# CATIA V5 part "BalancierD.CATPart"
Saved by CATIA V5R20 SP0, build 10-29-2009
Part number: BalancierD
Bounding box of the stored display mesh (mm): x 0 to 1, y 23.251 to 27.405, z -0.749 to 6.528
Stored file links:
  C:\Users\MATT\Desktop\CATIA_Projet_IAO\CATIA FINAL\BalancierD.CATPart
  C:\Users\MATT\Desktop\CATIA_Projet_IAO\CATIA FINAL\mderemetz.CATProduct
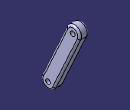
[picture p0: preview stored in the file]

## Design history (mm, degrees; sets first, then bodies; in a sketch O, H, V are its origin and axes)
External parameters (linked from other documents)
  External.AC = 3 mm
Set1
  Plane1 "Plan_Ref": linked copy from another document
  Point1 "B": linked copy from another document
  Point2 "F": linked copy from another document
  Plane2 "Plan_Sec": linked copy from another document
Body1 (main body)
  Sketch1 on Plane1, origin (0, 0, 0), H (0, 1, 0), V (0, 0, 1)
    construction line L1 (24.0001, 0) -> (26.6557, 5.779)
    point P1 (24.0001, 0)
    point P2 (26.6557, 5.779)
    line L2 (23.3186, 0.3132) -> (25.9743, 6.0921)
    line L3 (27.3372, 5.4658) -> (24.6816, -0.3132)
    arc A1 centre (26.6557, 5.779) radius 0.75 from (25.9743, 6.0921) to (27.3372, 5.4658) cw
    arc A2 centre (24.0001, 0) radius 0.75 from (24.6816, -0.3132) to (23.3186, 0.3132) cw
    reference projected point E1 (26.6557, 5.779) from Point1
    reference projected point E2 (24.0001, 0) from Point2
    distance L3 L2 = 1.5 {= 1.5*External.AC /3}
    tangency: A1 L2, A2 L2, A1 L3, A2 L3
    parallelism: L1 L2
    coincidence: P2 E1, P1 E2
  Pad1: profile Sketch1, direction (1, 0, 0), up to Plane2
  Sketch2 on end face of Pad1, origin (1, 25.1072, 2.6065), H (0, 1, 0), V (0, 0, 1)
    point P1 (1.5486, 3.1724)
    reference projected point E1 (1.5486, 3.1724) from Point1
    coincidence: P1 E1
  Hole1: placed by Sketch2, at (1, 26.6557, 5.779) direction (-1, 0, 0), diameter 0.5 {= 0.5*External.AC /3}, through (limit type 3)
  Sketch3 on end face of Pad1, origin (1, 24.878, 1.9969), H (0, 1, 0), V (0, 0, 1)
    point P1 (-0.8779, -1.9969)
    reference projected point E1 (-0.8779, -1.9969) from Point2
    coincidence: P1 E1
  Hole2: placed by Sketch3, at (1, 24.0001, 0) direction (-1, 0, 0), diameter 0.5 {= 0.5*External.AC /3}, through (limit type 3)
  Fillet1: radius 0.2 {= 0.2*External.AC /3}, on edge [end face of Pad1 | face of Pad1 from Sketch1.L2]; edge [start face of Pad1 | face of Pad1 from Sketch1.L2]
